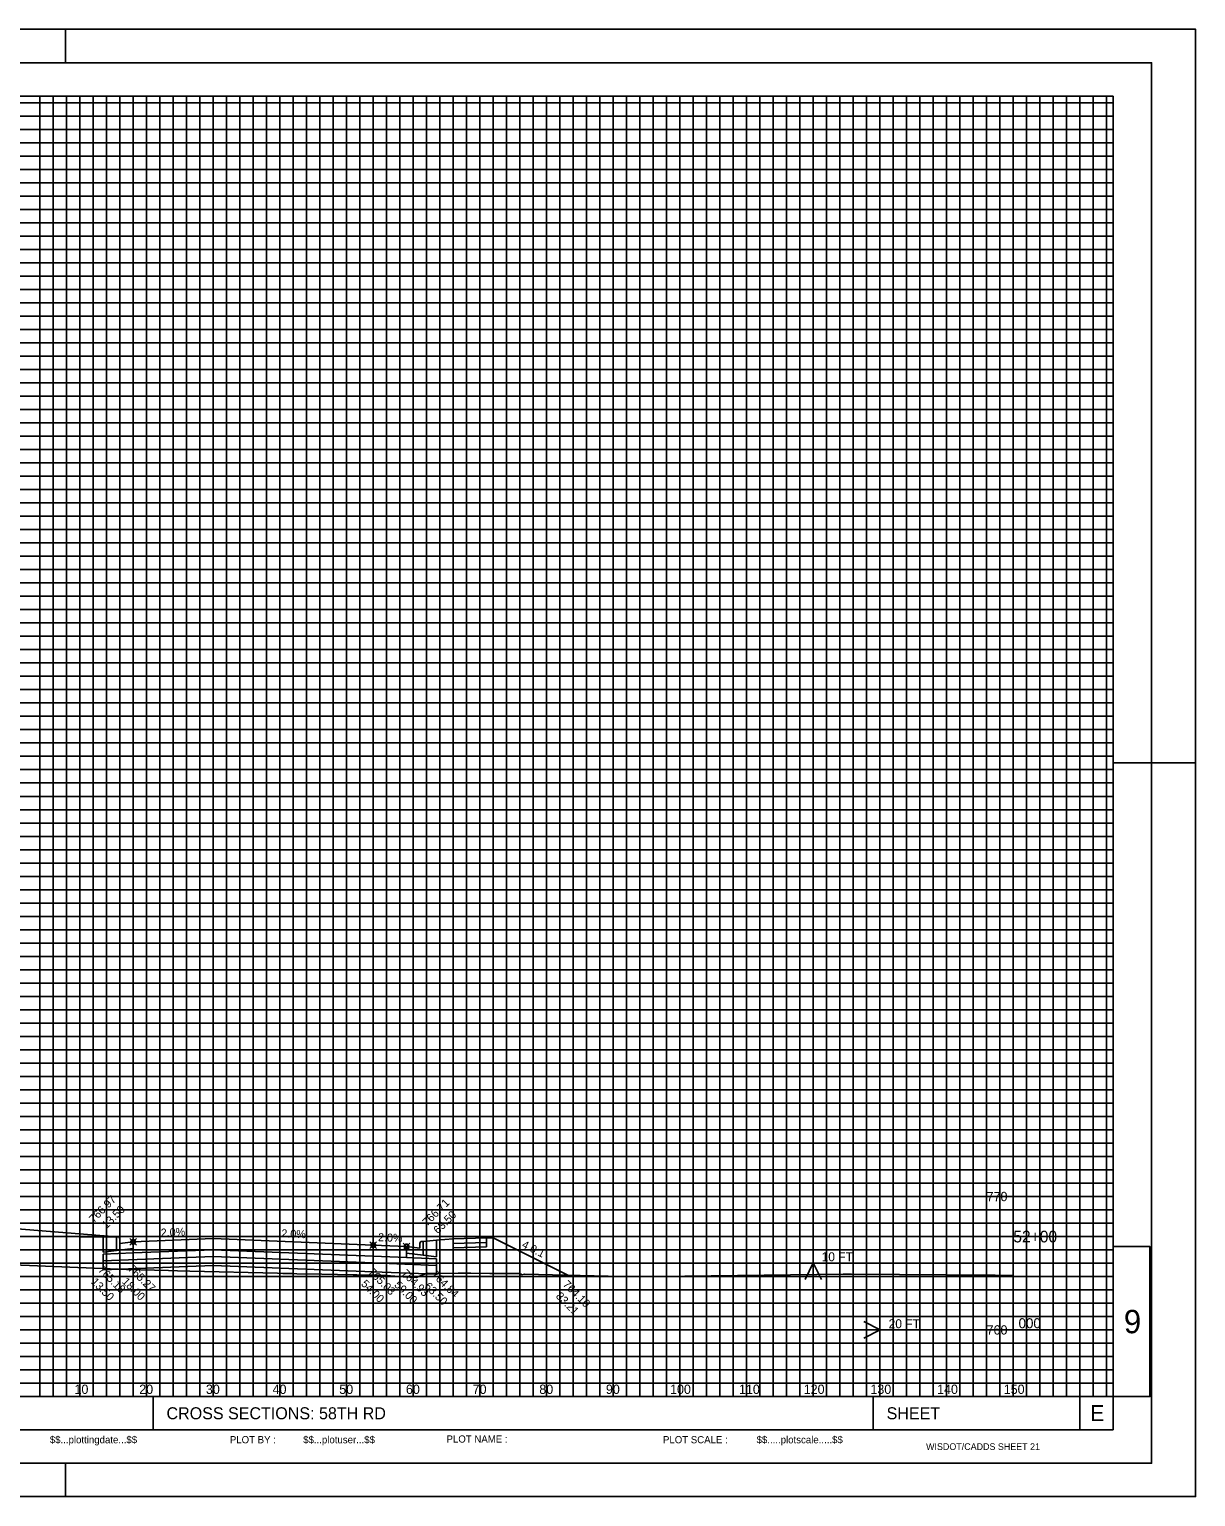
# Model space of a CAD drawing. Extents: x 578243 to 601557, y 174899 to 175559.
# Drawn here: x 601382.3 to 601557.2, y 174898.8 to 175118.8 of the extents above; entities that cross this region are included whole.
import ezdxf

# ---------------------------------------------------------------- set-up
doc = ezdxf.new("R2010")
doc.units = 0
for name, color, linetype in [('E_PROF_Grid', 7, 'Continuous'), ('E_PROF_GridMin', 7, 'Continuous'), ('P_CRDR_Label', 7, 'Continuous'), ('P_CRDR_Link', 7, 'Continuous'), ('P_E_XS_Ground', 7, 'Continuous'), ('P_XS_Text', 7, 'Continuous'), ('PLT_Sheet_Border', 7, 'Continuous'), ('PLT_Sheet_Info', 7, 'Continuous')]:
    doc.layers.add(name, color=color, linetype=linetype)

msp = doc.modelspace()

# ---------------------------------------------------------------- linework, layer by layer
at = {"layer": 'E_PROF_Grid'}
for p, q in [((601389.84, 174913.8), (601389.84, 175108.8)), ((601399.84, 174913.8), (601399.84, 175108.8)), ((601409.84, 174913.8), (601409.84, 175108.8)), ((601419.84, 174913.8), (601419.84, 175108.8)), ((601429.84, 174913.8), (601429.84, 175108.8)), ((601439.84, 174913.8), (601439.84, 175108.8)), ((601449.84, 174913.8), (601449.84, 175108.8)), ((601459.84, 174913.8), (601459.84, 175108.8)), ((601469.84, 174913.8), (601469.84, 175108.8)), ((601479.84, 174913.8), (601479.84, 175108.8)), ((601489.84, 174913.8), (601489.84, 175108.8)), ((601499.84, 174913.8), (601499.84, 175108.8)), ((601509.84, 174913.8), (601509.84, 175108.8)), ((601519.84, 174913.8), (601519.84, 175108.8)), ((601529.84, 174913.8), (601529.84, 175108.8)), ((601539.84, 174913.8), (601539.84, 175108.8)), ((601229.84, 175103.8), (601544.84, 175103.8)), ((601229.84, 175093.8), (601544.84, 175093.8)), ((601229.84, 175083.8), (601544.84, 175083.8)), ((601229.84, 175073.8), (601544.84, 175073.8)), ((601229.84, 175063.8), (601544.84, 175063.8)), ((601229.84, 175053.8), (601544.84, 175053.8)), ((601229.84, 175043.8), (601544.84, 175043.8)), ((601229.84, 175033.8), (601544.84, 175033.8)), ((601229.84, 175023.8), (601544.84, 175023.8)), ((601229.84, 175013.8), (601544.84, 175013.8)), ((601229.84, 175003.8), (601544.84, 175003.8)), ((601229.84, 174993.8), (601544.84, 174993.8)), ((601229.84, 174983.8), (601544.84, 174983.8)), ((601229.84, 174973.8), (601544.84, 174973.8)), ((601229.84, 174963.8), (601544.84, 174963.8)), ((601229.84, 174953.8), (601544.84, 174953.8)), ((601229.84, 174943.8), (601544.84, 174943.8)), ((601229.84, 174933.8), (601544.84, 174933.8)), ((601229.84, 174923.8), (601544.84, 174923.8))]:
    msp.add_line(p, q, dxfattribs=at)
at = {"layer": 'E_PROF_GridMin'}
for p, q in [((601229.84, 175107.8), (601544.84, 175107.8)), ((601383.84, 174913.8), (601383.84, 175108.8)), ((601385.84, 174913.8), (601385.84, 175108.8)), ((601387.84, 174913.8), (601387.84, 175108.8)), ((601391.84, 174913.8), (601391.84, 175108.8)), ((601393.84, 174913.8), (601393.84, 175108.8)), ((601395.84, 174913.8), (601395.84, 175108.8)), ((601397.84, 174913.8), (601397.84, 175108.8)), ((601401.84, 174913.8), (601401.84, 175108.8)), ((601403.84, 174913.8), (601403.84, 175108.8)), ((601405.84, 174913.8), (601405.84, 175108.8)), ((601407.84, 174913.8), (601407.84, 175108.8)), ((601411.84, 174913.8), (601411.84, 175108.8)), ((601413.84, 174913.8), (601413.84, 175108.8)), ((601415.84, 174913.8), (601415.84, 175108.8)), ((601417.84, 174913.8), (601417.84, 175108.8)), ((601421.84, 174913.8), (601421.84, 175108.8)), ((601423.84, 174913.8), (601423.84, 175108.8)), ((601425.84, 174913.8), (601425.84, 175108.8)), ((601427.84, 174913.8), (601427.84, 175108.8)), ((601431.84, 174913.8), (601431.84, 175108.8)), ((601433.84, 174913.8), (601433.84, 175108.8)), ((601435.84, 174913.8), (601435.84, 175108.8)), ((601437.84, 174913.8), (601437.84, 175108.8)), ((601441.84, 174913.8), (601441.84, 175108.8)), ((601443.84, 174913.8), (601443.84, 175108.8)), ((601445.84, 174913.8), (601445.84, 175108.8)), ((601447.84, 174913.8), (601447.84, 175108.8)), ((601451.84, 174913.8), (601451.84, 175108.8)), ((601453.84, 174913.8), (601453.84, 175108.8)), ((601455.84, 174913.8), (601455.84, 175108.8)), ((601457.84, 174913.8), (601457.84, 175108.8)), ((601461.84, 174913.8), (601461.84, 175108.8)), ((601463.84, 174913.8), (601463.84, 175108.8)), ((601465.84, 174913.8), (601465.84, 175108.8)), ((601467.84, 174913.8), (601467.84, 175108.8)), ((601471.84, 174913.8), (601471.84, 175108.8)), ((601473.84, 174913.8), (601473.84, 175108.8)), ((601475.84, 174913.8), (601475.84, 175108.8)), ((601477.84, 174913.8), (601477.84, 175108.8)), ((601481.84, 174913.8), (601481.84, 175108.8)), ((601483.84, 174913.8), (601483.84, 175108.8)), ((601485.84, 174913.8), (601485.84, 175108.8)), ((601487.84, 174913.8), (601487.84, 175108.8)), ((601491.84, 174913.8), (601491.84, 175108.8)), ((601493.84, 174913.8), (601493.84, 175108.8)), ((601495.84, 174913.8), (601495.84, 175108.8)), ((601497.84, 174913.8), (601497.84, 175108.8)), ((601501.84, 174913.8), (601501.84, 175108.8)), ((601503.84, 174913.8), (601503.84, 175108.8)), ((601505.84, 174913.8), (601505.84, 175108.8)), ((601507.84, 174913.8), (601507.84, 175108.8)), ((601511.84, 174913.8), (601511.84, 175108.8)), ((601513.84, 174913.8), (601513.84, 175108.8)), ((601515.84, 174913.8), (601515.84, 175108.8)), ((601517.84, 174913.8), (601517.84, 175108.8)), ((601521.84, 174913.8), (601521.84, 175108.8)), ((601523.84, 174913.8), (601523.84, 175108.8)), ((601525.84, 174913.8), (601525.84, 175108.8)), ((601527.84, 174913.8), (601527.84, 175108.8)), ((601531.84, 174913.8), (601531.84, 175108.8)), ((601533.84, 174913.8), (601533.84, 175108.8)), ((601535.84, 174913.8), (601535.84, 175108.8)), ((601537.84, 174913.8), (601537.84, 175108.8)), ((601541.84, 174913.8), (601541.84, 175108.8)), ((601543.84, 174913.8), (601543.84, 175108.8)), ((601229.84, 175105.8), (601544.84, 175105.8)), ((601229.84, 175101.8), (601544.84, 175101.8)), ((601229.84, 175099.8), (601544.84, 175099.8)), ((601229.84, 175097.8), (601544.84, 175097.8)), ((601229.84, 175095.8), (601544.84, 175095.8)), ((601229.84, 175091.8), (601544.84, 175091.8)), ((601229.84, 175089.8), (601544.84, 175089.8)), ((601229.84, 175087.8), (601544.84, 175087.8)), ((601229.84, 175085.8), (601544.84, 175085.8)), ((601229.84, 175081.8), (601544.84, 175081.8)), ((601229.84, 175079.8), (601544.84, 175079.8)), ((601229.84, 175077.8), (601544.84, 175077.8)), ((601229.84, 175075.8), (601544.84, 175075.8)), ((601229.84, 175071.8), (601544.84, 175071.8)), ((601229.84, 175069.8), (601544.84, 175069.8)), ((601229.84, 175067.8), (601544.84, 175067.8)), ((601229.84, 175065.8), (601544.84, 175065.8)), ((601229.84, 175061.8), (601544.84, 175061.8)), ((601229.84, 175059.8), (601544.84, 175059.8)), ((601229.84, 175057.8), (601544.84, 175057.8)), ((601229.84, 175055.8), (601544.84, 175055.8)), ((601229.84, 175051.8), (601544.84, 175051.8)), ((601229.84, 175049.8), (601544.84, 175049.8)), ((601229.84, 175047.8), (601544.84, 175047.8)), ((601229.84, 175045.8), (601544.84, 175045.8)), ((601229.84, 175041.8), (601544.84, 175041.8)), ((601229.84, 175039.8), (601544.84, 175039.8)), ((601229.84, 175037.8), (601544.84, 175037.8)), ((601229.84, 175035.8), (601544.84, 175035.8)), ((601229.84, 175031.8), (601544.84, 175031.8)), ((601229.84, 175029.8), (601544.84, 175029.8)), ((601229.84, 175027.8), (601544.84, 175027.8)), ((601229.84, 175025.8), (601544.84, 175025.8)), ((601229.84, 175021.8), (601544.84, 175021.8)), ((601229.84, 175019.8), (601544.84, 175019.8)), ((601229.84, 175017.8), (601544.84, 175017.8)), ((601229.84, 175015.8), (601544.84, 175015.8)), ((601229.84, 175011.8), (601544.84, 175011.8)), ((601229.84, 175009.8), (601544.84, 175009.8)), ((601229.84, 175007.8), (601544.84, 175007.8)), ((601229.84, 175005.8), (601544.84, 175005.8)), ((601229.84, 175001.8), (601544.84, 175001.8)), ((601229.84, 174999.8), (601544.84, 174999.8)), ((601229.84, 174997.8), (601544.84, 174997.8)), ((601229.84, 174995.8), (601544.84, 174995.8)), ((601229.84, 174991.8), (601544.84, 174991.8)), ((601229.84, 174989.8), (601544.84, 174989.8)), ((601229.84, 174987.8), (601544.84, 174987.8)), ((601229.84, 174985.8), (601544.84, 174985.8)), ((601229.84, 174981.8), (601544.84, 174981.8)), ((601229.84, 174979.8), (601544.84, 174979.8)), ((601229.84, 174977.8), (601544.84, 174977.8)), ((601229.84, 174975.8), (601544.84, 174975.8)), ((601229.84, 174971.8), (601544.84, 174971.8)), ((601229.84, 174969.8), (601544.84, 174969.8)), ((601229.84, 174967.8), (601544.84, 174967.8)), ((601229.84, 174965.8), (601544.84, 174965.8)), ((601229.84, 174961.8), (601544.84, 174961.8)), ((601229.84, 174959.8), (601544.84, 174959.8)), ((601229.84, 174957.8), (601544.84, 174957.8)), ((601229.84, 174955.8), (601544.84, 174955.8)), ((601229.84, 174951.8), (601544.84, 174951.8)), ((601229.84, 174949.8), (601544.84, 174949.8)), ((601229.84, 174947.8), (601544.84, 174947.8)), ((601229.84, 174945.8), (601544.84, 174945.8)), ((601229.84, 174941.8), (601544.84, 174941.8)), ((601229.84, 174939.8), (601544.84, 174939.8)), ((601229.84, 174937.8), (601544.84, 174937.8)), ((601229.84, 174935.8), (601544.84, 174935.8)), ((601229.84, 174931.8), (601544.84, 174931.8)), ((601229.84, 174929.8), (601544.84, 174929.8)), ((601229.84, 174927.8), (601544.84, 174927.8)), ((601229.84, 174925.8), (601544.84, 174925.8)), ((601229.84, 174921.8), (601544.84, 174921.8)), ((601229.84, 174919.8), (601544.84, 174919.8)), ((601229.84, 174917.8), (601544.84, 174917.8)), ((601229.84, 174915.8), (601544.84, 174915.8)), ((601557.19, 174898.8), (601557.19, 174908.8)), ((601547.19, 174898.8), (601557.19, 174898.8))]:
    msp.add_line(p, q, dxfattribs=at)
at = {"layer": 'P_CRDR_Label'}
for points in [[(601397.34, 174936.5), (601398.33, 174937.49)], [(601397.34, 174937.49), (601398.33, 174936.5)], [(601433.34, 174936.02), (601434.33, 174937.01)], [(601433.34, 174937.01), (601434.33, 174936.02)], [(601438.34, 174935.82), (601439.33, 174936.81)], [(601438.34, 174936.81), (601439.33, 174935.82)]]:
    msp.add_lwpolyline(points, dxfattribs=at)
for centre in [(601397.84, 174937), (601433.84, 174936.52), (601438.84, 174936.32)]:
    msp.add_circle(centre, 0.35, dxfattribs=at)
at = {"layer": 'P_CRDR_Link'}
for points in [[(601395.34, 174937.75), (601379.84, 174938.99)], [(601395.34, 174937.75), (601379.84, 174938.99)], [(601393.34, 174937.73), (601389.84, 174937.7)], [(601393.34, 174937.73), (601389.84, 174937.7)], [(601395.34, 174937.75), (601393.34, 174937.73)], [(601393.34, 174937.73), (601393.34, 174935.43)], [(601393.34, 174937.73), (601393.34, 174935.43)], [(601393.34, 174937.73), (601393.34, 174935.43)], [(601395.66, 174937.75), (601395.34, 174937.75)], [(601395.66, 174937.75), (601395.34, 174937.75)], [(601395.34, 174937.75), (601395.34, 174935.68)], [(601395.34, 174935.68), (601395.34, 174937.75)], [(601395.74, 174937.7), (601395.66, 174937.75)], [(601395.74, 174937.7), (601395.66, 174937.75)], [(601395.8, 174937.59), (601395.74, 174937.7)], [(601395.8, 174937.59), (601395.74, 174937.7)], [(601395.82, 174937.43), (601395.8, 174937.59)], [(601395.82, 174937.43), (601395.8, 174937.59)], [(601395.84, 174936.75), (601395.82, 174937.43)], [(601395.84, 174936.75), (601395.82, 174937.43)], [(601397.84, 174937), (601409.84, 174937.48)], [(601409.84, 174937.48), (601409.84, 174935.81)], [(601409.84, 174937.48), (601433.84, 174936.52)], [(601409.84, 174937.48), (601409.84, 174935.81)], [(601443.34, 174937.23), (601445.84, 174937.43)], [(601443.34, 174937.23), (601445.84, 174937.43)], [(601445.84, 174937.43), (601450.84, 174937.58)], [(601445.84, 174937.43), (601450.84, 174937.58)], [(601445.84, 174937.43), (601445.84, 174936.76)], [(601450.84, 174937.58), (601450.83, 174936.91)], [(601450.84, 174937.58), (601451.84, 174937.61)], [(601450.84, 174937.58), (601451.84, 174937.61)], [(601451.84, 174937.61), (601463.05, 174932)], [(601451.84, 174937.61), (601463.05, 174932)], [(601393.34, 174935.43), (601395.34, 174935.68)], [(601393.34, 174935.15), (601397.84, 174935.33)], [(601395.34, 174935.68), (601397.84, 174936)], [(601395.34, 174935.68), (601397.84, 174936)], [(601397.84, 174937), (601395.84, 174936.75)], [(601397.84, 174937), (601395.84, 174936.75)], [(601397.84, 174936), (601397.84, 174937)], [(601397.84, 174937), (601397.84, 174935.33)], [(601397.84, 174935.33), (601409.84, 174935.81)], [(601409.84, 174935.81), (601409.84, 174934.81)], [(601409.84, 174935.81), (601433.84, 174934.85)], [(601409.84, 174935.81), (601409.84, 174934.81)], [(601433.84, 174936.52), (601433.84, 174934.85)], [(601433.84, 174936.52), (601438.84, 174936.32)], [(601433.84, 174936.52), (601433.84, 174934.85)], [(601438.84, 174936.32), (601438.84, 174934.65)], [(601438.84, 174936.32), (601440.84, 174936.07)], [(601438.84, 174936.32), (601440.84, 174936.07)], [(601438.84, 174935.32), (601438.84, 174936.32)], [(601441.34, 174935), (601438.84, 174935.32)], [(601441.34, 174935), (601438.84, 174935.32)], [(601440.84, 174936.07), (601440.85, 174936.75)], [(601440.84, 174936.07), (601440.85, 174936.75)], [(601440.85, 174936.75), (601440.88, 174936.91)], [(601440.85, 174936.75), (601440.88, 174936.91)], [(601440.88, 174936.91), (601440.94, 174937.02)], [(601440.88, 174936.91), (601440.94, 174937.02)], [(601440.94, 174937.02), (601441.02, 174937.07)], [(601440.94, 174937.02), (601441.02, 174937.07)], [(601441.02, 174937.07), (601441.34, 174937.07)], [(601441.02, 174937.07), (601441.34, 174937.07)], [(601441.34, 174937.07), (601443.34, 174937.23)], [(601441.34, 174937.07), (601441.34, 174935)], [(601441.34, 174935), (601441.34, 174937.07)], [(601443.34, 174937.23), (601443.34, 174934.75)], [(601443.34, 174937.23), (601443.34, 174934.75)], [(601443.34, 174937.23), (601443.34, 174934.75)], [(601445.84, 174936.76), (601450.83, 174936.91)], [(601445.84, 174936.76), (601445.85, 174936.1)], [(601445.85, 174936.1), (601450.83, 174936.25)], [(601450.83, 174936.25), (601450.83, 174936.91)], [(601393.34, 174935.15), (601393.34, 174934.15)], [(601393.34, 174934.15), (601409.84, 174934.81)], [(601393.34, 174934.15), (601393.34, 174932.82)], [(601393.34, 174932.82), (601409.84, 174933.48)], [(601409.84, 174934.81), (601409.84, 174933.48)], [(601409.84, 174934.81), (601433.84, 174933.85)], [(601409.84, 174934.81), (601409.84, 174933.48)], [(601409.84, 174933.48), (601433.84, 174932.52)], [(601433.84, 174934.85), (601433.84, 174933.85)], [(601433.84, 174934.85), (601438.84, 174934.65)], [(601433.84, 174934.85), (601433.84, 174933.85)], [(601433.84, 174933.85), (601433.84, 174932.52)], [(601433.84, 174933.85), (601443.34, 174933.47)], [(601433.84, 174933.85), (601433.84, 174932.52)], [(601438.84, 174934.65), (601443.34, 174934.47)], [(601443.34, 174934.75), (601441.34, 174935)], [(601443.34, 174934.47), (601443.34, 174933.47)], [(601443.34, 174933.47), (601443.34, 174932.14)], [(601433.84, 174932.52), (601443.34, 174932.14)]]:
    msp.add_lwpolyline(points, dxfattribs=at)
at = {"layer": 'P_E_XS_Ground'}
msp.add_lwpolyline([(601379.84, 174933.56), (601396.84, 174932.88), (601403.13, 174932.71), (601404.49, 174932.67), (601406.35, 174932.63), (601419.48, 174932.29), (601420.27, 174932.28), (601421.75, 174932.25), (601422.37, 174932.23), (601426.11, 174932.16), (601430.85, 174932.07), (601431.24, 174932.06), (601431.39, 174932.06), (601435, 174931.99), (601436.45, 174931.89), (601438.34, 174931.78), (601440.29, 174931.66), (601441.66, 174932.2), (601441.99, 174932.3), (601443.07, 174932.28), (601443.49, 174932.27), (601446.59, 174932.29), (601448.46, 174932.29), (601451.32, 174932.28), (601453.07, 174932.27), (601455.93, 174932.24), (601456.09, 174932.08), (601456.51, 174932.16), (601471.19, 174931.81), (601480.57, 174931.85), (601504.33, 174932.15), (601505.39, 174932.14), (601505.58, 174932.14), (601527.11, 174931.99), (601529.84, 174931.97)], dxfattribs=at)
at = {"layer": 'PLT_Sheet_Border'}
for points in [[(601217.19, 174898.8), (601557.19, 174898.8), (601557.19, 175118.8), (601217.19, 175118.8)], [(601219.59, 174903.8), (601550.59, 174903.8), (601550.59, 175113.8), (601219.59, 175113.8)]]:
    msp.add_lwpolyline(points, close=True, dxfattribs=at)
at = {"layer": 'PLT_Sheet_Info'}
for p, q in [((601382.69, 175118.8), (601392.69, 175118.8)), ((601387.69, 175118.8), (601387.69, 175113.8)), ((601547.19, 175118.8), (601557.19, 175118.8)), ((601557.19, 175108.8), (601557.19, 175118.8)), ((601229.84, 175108.8), (601544.84, 175108.8)), ((601544.84, 174908.8), (601544.84, 175108.8)), ((601557.19, 175003.8), (601557.19, 175013.8)), ((601557.19, 175008.8), (601544.84, 175008.8)), ((601229.84, 174913.8), (601544.84, 174913.8)), ((601400.84, 174908.8), (601400.84, 174913.8)), ((601508.84, 174908.8), (601508.84, 174913.8)), ((601539.84, 174908.8), (601539.84, 174913.8)), ((601229.84, 174908.8), (601544.84, 174908.8)), ((601387.69, 174898.8), (601387.69, 174903.8)), ((601382.69, 174898.8), (601392.69, 174898.8))]:
    msp.add_line(p, q, dxfattribs=at)
msp.add_lwpolyline([(601544.84, 174936.3), (601550.34, 174936.3), (601550.34, 174913.8), (601544.84, 174913.8)], close=True, dxfattribs=at)
for points in [[(601499.84, 174933.84), (601498.6, 174931.36)], [(601499.84, 174923.8), (601499.84, 174933.84), (601501.08, 174931.36)], [(601509.89, 174923.8), (601507.4, 174925.04)], [(601499.84, 174923.8), (601509.89, 174923.8), (601507.4, 174922.55)]]:
    msp.add_lwpolyline(points, dxfattribs=at)

# ---------------------------------------------------------------- texts
at = {"layer": 'P_CRDR_Label'}
for s, rotation, p in [('766.97', 45, (601391.92, 174939.77)), ('13.50', 45, (601393.87, 174938.89)), ('766.71', 45, (601441.92, 174939.27)), ('63.50', 45, (601443.58, 174938.1)), ('2.0%', 2.2906, (601402, 174937.78)), ('2.0%', 357.7094, (601420.05, 174937.69)), ('2.0%', 357.7094, (601434.55, 174937.11)), ('4.0:1', 333.4349, (601456.02, 174936.21)), ('765.18', 315, (601392.49, 174932.67)), ('765.27', 315, (601396.99, 174932.85)), ('765.03', 315, (601432.99, 174932.37)), ('13.50', 315, (601391.43, 174930.91)), ('18.00', 315, (601396.07, 174930.94)), ('54.00', 315, (601431.93, 174930.61)), ('59.00', 315, (601436.9, 174930.44)), ('764.93', 315, (601437.99, 174932.17)), ('63.50', 315, (601441.43, 174930.23)), ('764.84', 315, (601442.49, 174931.99)), ('764.10', 315, (601462.2, 174930.52)), ('764.10', 315, (601462.2, 174930.52)), ('83.21', 315, (601461.14, 174928.76)), ('83.21', 315, (601461.14, 174928.76))]:
    msp.add_text(s, height=1.2, rotation=rotation, dxfattribs=at).set_placement(p)
at = {"layer": 'P_XS_Text'}
for s, height, p in [('770', 1.4, (601525.84, 174943.1)), ('52+00', 1.75, (601529.84, 174936.92)), ('760', 1.4, (601525.84, 174923.1)), ('10', 1.4, (601389.04, 174914.2)), ('20', 1.4, (601398.75, 174914.2)), ('30', 1.4, (601408.75, 174914.2)), ('40', 1.4, (601418.75, 174914.2)), ('50', 1.4, (601428.75, 174914.2)), ('60', 1.4, (601438.75, 174914.2)), ('70', 1.4, (601448.75, 174914.2)), ('80', 1.4, (601458.75, 174914.2)), ('90', 1.4, (601468.74, 174914.2)), ('100', 1.4, (601478.36, 174914.2)), ('110', 1.4, (601488.7, 174914.2)), ('120', 1.4, (601498.41, 174914.2)), ('130', 1.4, (601508.41, 174914.2)), ('140', 1.4, (601518.41, 174914.2)), ('150', 1.4, (601528.41, 174914.2))]:
    msp.add_text(s, height=height, rotation=360, dxfattribs=at).set_placement(p)
at = {"layer": 'PLT_Sheet_Info'}
for s, height, p in [('  10 FT', 1.347, (601500.09, 174934.09)), ('9', 3.5, (601546.42, 174923.3)), ('  20 FT', 1.347, (601510.14, 174924.05)), ('     000', 1.5, (601527.84, 174924.05)), ('CROSS SECTIONS: 58TH RD                           ', 1.8, (601402.84, 174910.4)), ('SHEET ', 1.8, (601510.84, 174910.4)), ('E', 2.4, (601541.36, 174910.12)), ('PLOT NAME :                      ', 1.08, (601444.84, 174906.9)), ('PLOT SCALE : ', 1.08, (601477.3, 174906.8)), ('$$.....plotscale.....$$', 1.08, (601491.34, 174906.8)), ('WISDOT/CADDS SHEET 21', 1, (601516.76, 174905.8))]:
    msp.add_text(s, height=height, dxfattribs=at).set_placement(p)
for s, p in [('$$...plottingdate...$$', (601385.34, 174906.8)), ('PLOT BY :', (601412.34, 174906.8)), ('$$...plotuser...$$', (601423.34, 174906.8))]:
    msp.add_text(s, height=1.08, rotation=360, dxfattribs=at).set_placement(p)

doc.saveas('drawing.dxf')
